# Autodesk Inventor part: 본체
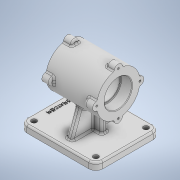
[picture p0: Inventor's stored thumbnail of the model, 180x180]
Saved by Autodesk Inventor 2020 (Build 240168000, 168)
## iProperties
Created: 2022-11
Part Number: 본체
Material: 일반
Document SubType Name: Modeling
Designer: owner
Density: 1 g/cm^3
Appearance: 기본값
Mass: 450.145 g
Surface Area: 796.917 cm^2
Volume: 450.145 cm^3
Author: owner
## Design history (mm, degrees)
sketch "스케치1"
  geometry: L1 (65, 55)-(-65, 55); L2 (-65, 55)-(-65, -55); L3 (-65, -55)-(65, -55); L4 (65, -55)-(65, 55); L5 (65, 55)-(-65, -55); L6 (-65, 55)-(65, -55); 1 further point
  constraints: 12 end point, 2 midpoint, 2 parallel, 1 horizontal, 1 perpendicular
  dimensions: "d0" = 130 distance of L3.end L2.end; "d1" = 110 distance of L2.end L1.end
extrude "돌출1" new body sketch "스케치1" distance "d2" = 12; taper "d3" = 0 deg
node "작업 평면1"
sketch "스케치2"
  geometry: L1 (0, 0)-(110, 0) reference; C1 r 37 at (55, 82); 2 further points
  constraints: 1 centre point, 1 midpoint, 1 vertical alignment
  dimensions: "d5" = 74 diameter of C1; "d6" = 82 distance from line of L1 C1.centre
extrude "돌출2" join sketch "스케치2" stored distance "d7" = 87; taper "d8" = 0 deg
sketch "스케치3"
  geometry: C1 r 37 at (0, 0) reference; 2 further points
  constraints: 1 coincident
hole "구멍1" sketch "스케치3" at (0, 0) diameter "d9" = 42; stored, may be unused: countersink angle "d13" = 90 deg, drill point angle "d15" = 0 deg; dims "d10" = 8, "d11" = 47, "d12" = 19, "d14" = 10
sketch "스케치4"
  geometry: C1 r 37 at (0, 0) reference; 2 further points
  constraints: 1 coincident
hole "구멍2" sketch "스케치4" at (0, 0) diameter "d16" = 42; stored, may be unused: countersink angle "d20" = 90 deg, drill point angle "d22" = 0 deg; dims "d17" = 8, "d18" = 47, "d19" = 19, "d21" = 10
sketch "스케치5"
  geometry: L1 (110, 12)-(0, 12) reference; L2 (110, 0)-(110, 12) reference; L3 (0, 0)-(0, 12) reference; L4 (96, 12)-(80.336, 55.036); L5 (14, 12)-(29.664, 55.036); A1 r 37 centre (55, 82) between (80.336, 55.036) and (29.664, 55.036) reference; 1 further point
  constraints: 4 end point, 2 point on circle, 2 point on line
  dimensions: "d25" = 14 distance from line of L2 L4.start; "d26" = 14 distance from line of L3 L5.start; "d27" = 110 deg angle of L1 L4; "d28" = 110 deg angle of L1 L5
extrude "돌출3" join sketch "스케치5" stored distance "d29" = 10; taper "d30" = 0 deg
sketch "스케치6"
  geometry: L1 (65, 12)-(-65, 12) reference; L2 (-15, 12)-(-15, 28.945); L3 (25, 12)-(25, 27.739); L4 (5, -23.8)-(5, 142.8) reference; 1 further point
  constraints: 4 end point, 2 point on line, 2 vertical
  dimensions: "d31" = 40 distance between parallel lines of L3 L2; "d32" = 20 distance between parallel lines of L4 L2
feature "리브1" sketch "스케치6" dims "d33" = 1, "d34" = 10, "d35" = 0, "d36" = 0, "d37" = 1, "d38" = 1
sketch "스케치7"
  geometry: C1 r 7 at (0, 37); 4 further points
  constraints: 1 centre point, 1 vertical alignment, 2 other
  dimensions: "d39" = 14 diameter of C1
extrude "돌출4" join sketch "스케치7" distance "d40" = 14; taper "d41" = 0 deg
sketch "스케치8"
  geometry: A1 r 7 centre (-55, 119) between (-48.031, 118.338) and (-61.969, 118.338) reference; 2 further points
  constraints: 1 coincident
hole "구멍3" sketch "스케치8" at (-55, 119) diameter "d42" = 3.242; stored, may be unused: countersink angle "d46" = 90 deg, drill point angle "d48" = 118 deg; dims "d43" = 8, "d44" = 47, "d45" = 19, "d47" = 10
fillet "모깎기1" dims "d49" = 3
fillet "모깎기2" dims "d50" = 3
fillet "모깎기3" dims "d54" = 12
sketch "스케치9"
  geometry: A1 r 12 centre (53, -43) between (53, -55) and (65, -43) reference; 2 further points
  constraints: 1 coincident
hole "구멍4" sketch "스케치9" at (53, -43) diameter "d55" = 9; stored, may be unused: countersink angle "d59" = 90 deg, drill point angle "d61" = 118 deg; dims "d56" = 8, "d57" = 47, "d58" = 19, "d60" = 10
sketch "스케치10"
  geometry: A1 r 12 centre (-53, -43) between (-65, -43) and (-53, -55) reference; A2 r 12 centre (-53, 43) between (-53, 55) and (-65, 43) reference; A3 r 12 centre (53, 43) between (65, 43) and (53, 55) reference; 4 further points
  constraints: 3 coincident
hole "구멍5" sketch "스케치10" at (-53, -43), (-53, 43), (53, 43) diameter "d62" = 9; stored, may be unused: countersink angle "d66" = 90 deg, drill point angle "d68" = 118 deg; dims "d63" = 8, "d64" = 47, "d65" = 19, "d67" = 10
fillet "모깎기4" dims "d69" = 3
fillet "모깎기5" dims "d70" = 3
fillet "모깎기6" dims "d71" = 3
fillet "모깎기7" dims "d72" = 3
fillet "모깎기8" dims "d73" = 1
fillet "모깎기9" dims "d74" = 1
chamfer "모따기1" distance "d75" = 1; stored, may be unused: second distance "d76" = 2, angle "d77" = 45 deg
sketch "스케치11"
  geometry: L1 (5, -77)-(5, 77) reference; 2 further points
  constraints: 1 horizontal alignment, 1 other
  dimensions: "d78" = 58 distance from line of L1 point (-53, 0)
feature "엠보싱1" sketch "스케치11" dims "d0" = 130, "d1" = 110, "d79" = 0.5, "d80" = 0
node "솔리드1"
mirror "미러1"
pattern_circular "원형 패턴1" dims "d52" = 360 deg
mirror "미러2"
feature "A9D066F2-1C7D-4E18-AEED-F7BC21143FA4" dims "d9" = 42, "d10" = 8, "d11" = 47, "d12" = 19, "d13" = 90 deg, "d14" = 10, "d15" = 0
